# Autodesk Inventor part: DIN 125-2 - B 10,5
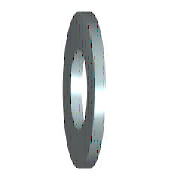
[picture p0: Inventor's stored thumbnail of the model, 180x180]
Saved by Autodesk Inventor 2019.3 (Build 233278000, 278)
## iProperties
Created: 2018-01
Part Number: DIN 125-2 - B 10,5
Material: Ocel, měkká
Description: Podložka
Document SubType Name: Modeling
Standard: DIN 125-2
Designer: B-hon
Standards Organization: DIN
Language: cs-CZ
Size Designation: B 10,5
Categories: <MemberInstance><Categories><Category DisplayName="Spojovací materiál" InternalName="e4da775c-781d-43d5-af7c-5136215cf5a6" Mnemonic="FSTN"><Category DisplayName
Density: 7.85 g/cm^3
Appearance: Pololeštěná
IsCustomPart: 0
Author: B-hon
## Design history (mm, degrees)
sketch "Náčrt"
  geometry: C1 r 10 at (0, 0); C2 r 5.25 at (0, 0); 1 further point
  constraints: 2 centre point, 2 coincident
  dimensions: "d0" = 10.5 diameter of C2 (= SD1); "d1" = 20 diameter of C1 (= SD2)
extrude "Těleso" new body sketch "Náčrt" distance "d2" = 2 (= SD); taper "d3" = 0 deg
workaxis "Work Axis1"
workplane "Work Plane1"
body "Solid1"
other parameters: "SD1" = 10.5 [user parameter; used in 1 equation term], "SD2" = 20 [user parameter; used in 1 equation term], "SD" = 2 [user parameter; used in 1 equation term], "d4" = 0, "d5" = 0, "d6" = 0, "d7" = 0
